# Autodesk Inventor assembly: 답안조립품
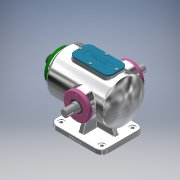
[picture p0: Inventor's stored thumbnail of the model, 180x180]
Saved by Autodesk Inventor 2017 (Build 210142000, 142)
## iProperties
Part Number: 답안조립품
Material: 일반
Document SubType Name: Assembly
Designer: Administrator
Author: Administrator
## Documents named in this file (14)
- C:\Users\Administrator\Desktop\711106V1017\답안조립품.iam
- C:\Users\Administrator\Desktop\711106V1017\본체.ipt
- C:\Users\Administrator\Desktop\711106V1017\베어링 6205.ipt
- 베어링 6205.ipt
- C:\Users\Administrator\Desktop\711106V1017\축 커버.ipt
- C:\Users\Administrator\Desktop\711106V1017\오일실.ipt
- 오일실.ipt
- C:\Users\Administrator\Desktop\711106V1017\슬라이드 커버.ipt
- C:\Users\Administrator\Desktop\711106V1017\부시.ipt
- C:\Users\Administrator\Desktop\711106V1017\슬라이드.ipt
- C:\Users\Administrator\Desktop\711106V1017\편심축.ipt
- C:\Users\Administrator\Desktop\711106V1017\상부커버.ipt
- C:\Users\Administrator\Desktop\711106V1017\육각머리볼트 M4.ipt
- C:\Users\Administrator\Desktop\711106V1017\볼트 M4x0.7.ipt
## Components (12 placed, 1 different names)
1. M4x0.7:1
2. M4x0.7:2
3. M4x0.7:3
4. M4x0.7:4
5. M4x0.7:9
6. M4x0.7:10
7. M4x0.7:11
8. M4x0.7:12
9. M4x0.7:8
10. M4x0.7:13
11. M4x0.7:14
12. M4x0.7:15
